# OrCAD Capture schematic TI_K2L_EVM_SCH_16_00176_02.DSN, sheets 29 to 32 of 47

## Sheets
29 PAGE17 : K2L_SOC-FPGA-AMC-3: size C; title: FPGA, K2L SPI/TIM/UART, FPGA test conn
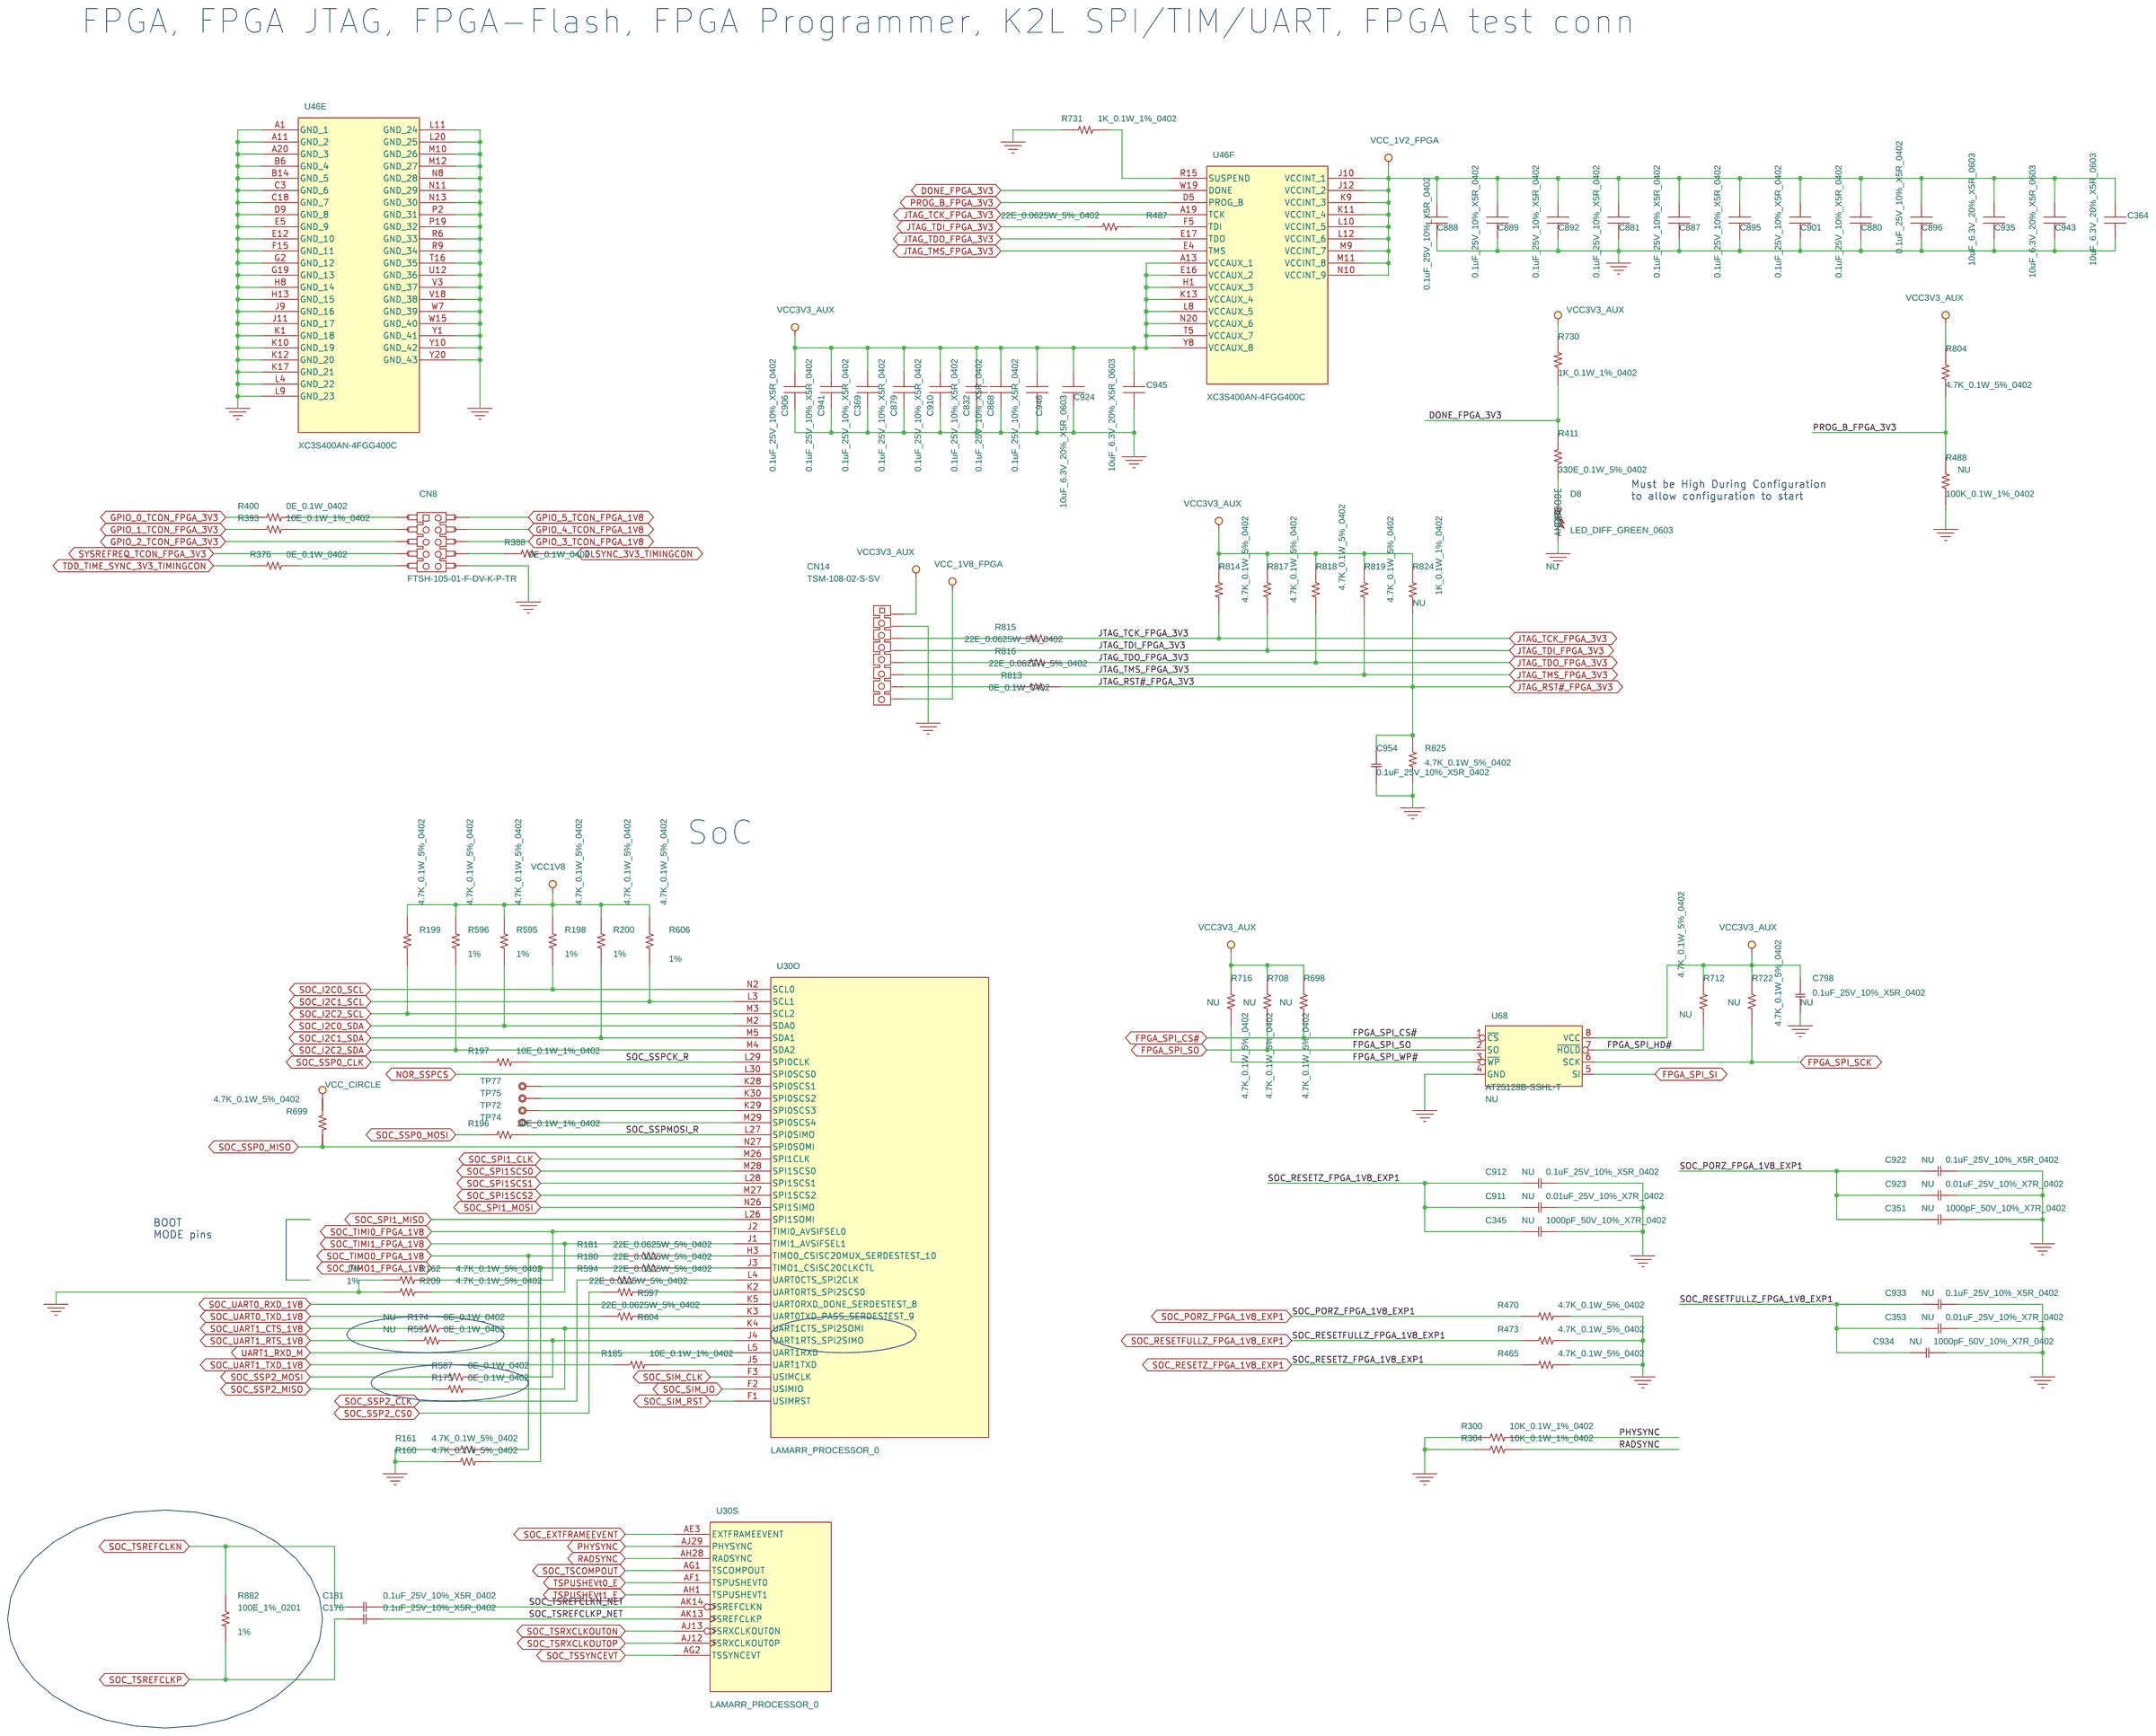
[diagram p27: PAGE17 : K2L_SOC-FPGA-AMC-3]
30 PAGE05 : POWER CONSUMPTION_C: title: POWER CONSUMPTION
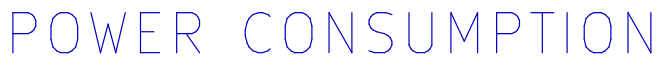
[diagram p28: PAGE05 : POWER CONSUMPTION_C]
31 PAGE02 : TABLE OF CONTENTS_C: title: TABLE OF CONTENTS
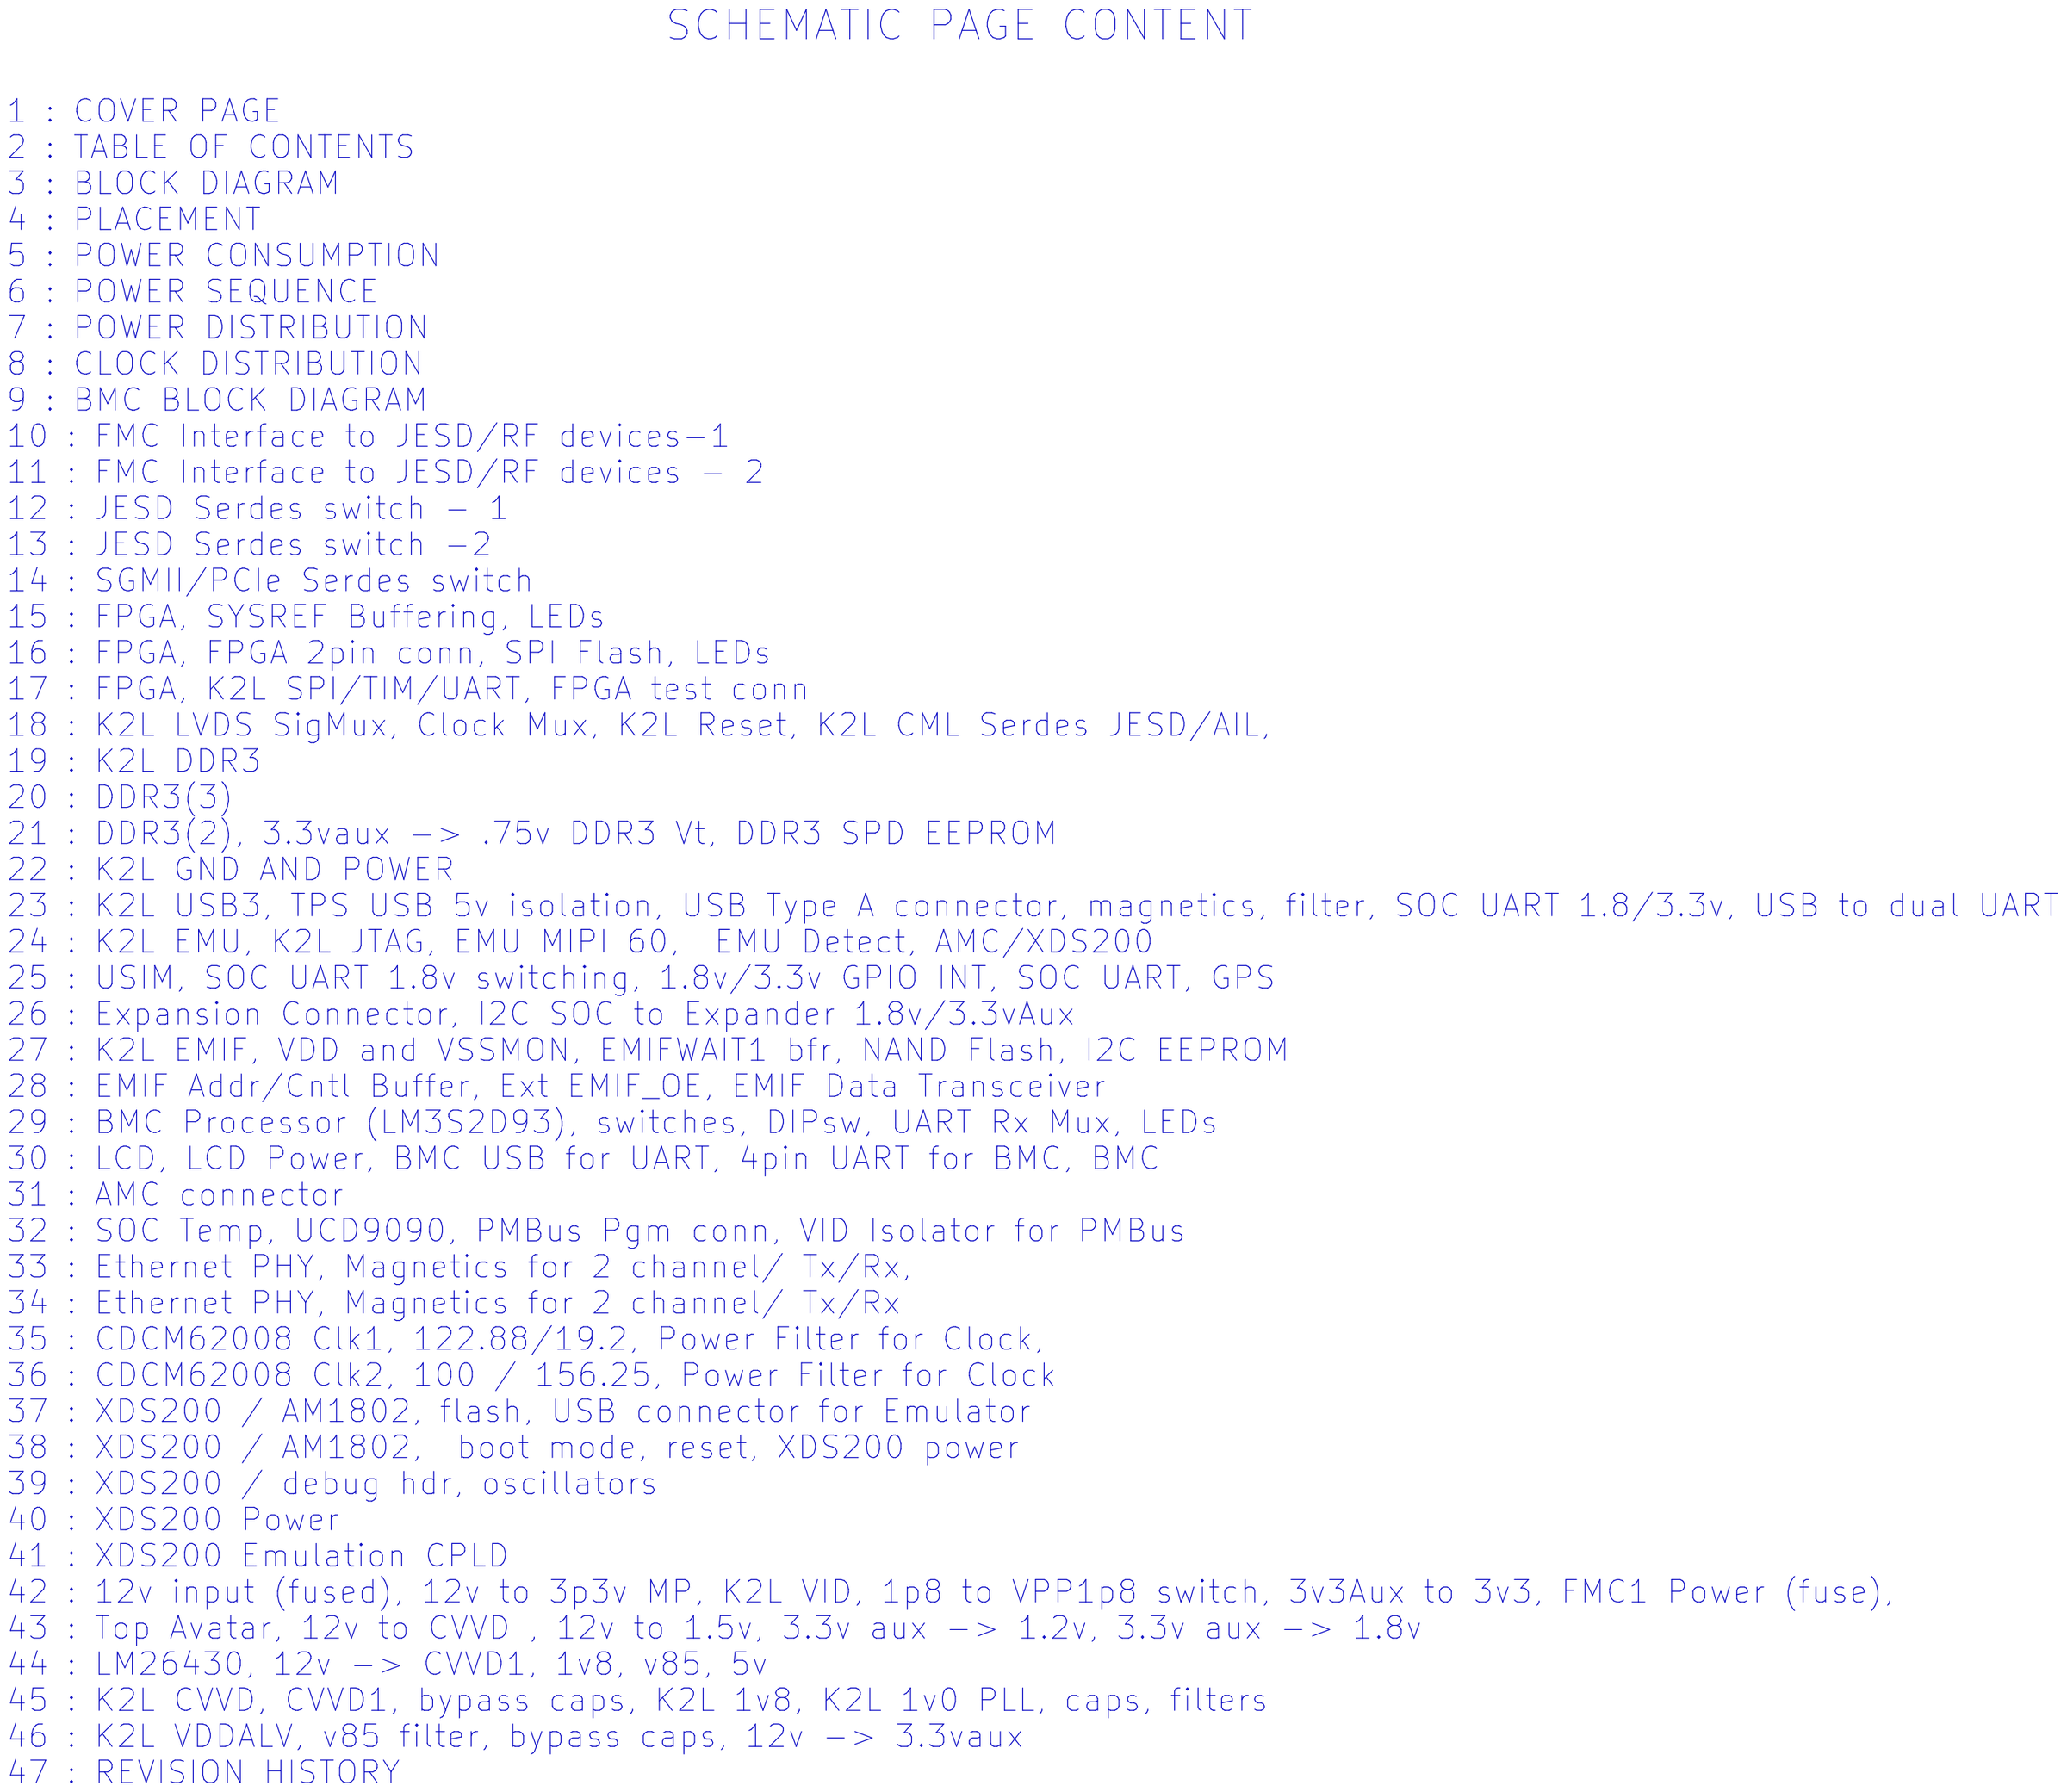
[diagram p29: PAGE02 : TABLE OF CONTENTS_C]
32 PAGE09 : BMC BLOCK DIAGRAM_C: title: BMC BLOCK DIAGRAM; note: K2E EVM
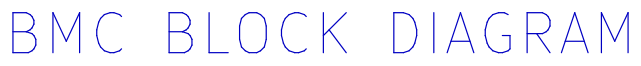
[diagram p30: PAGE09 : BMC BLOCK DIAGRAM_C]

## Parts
sheet PAGE17 : K2L_SOC-FPGA-AMC-3
C176  0.1uF_25V_10%_X5R_0402  [C0402]
C181  0.1uF_25V_10%_X5R_0402  [C0402]
C345  1000pF_50V_10%_X7R_0402  [C0402]
C351  1000pF_50V_10%_X7R_0402  [C0402]
C353  0.01uF_25V_10%_X7R_0402  [C0402]
C364  10uF_6.3V_20%_X5R_0603  [C0603]
C369  0.1uF_25V_10%_X5R_0402  [C0402]
C798  0.1uF_25V_10%_X5R_0402  [C0402]
C832  0.1uF_25V_10%_X5R_0402  [C0402]
C868  0.1uF_25V_10%_X5R_0402  [C0402]
C879  0.1uF_25V_10%_X5R_0402  [C0402]
C880  0.1uF_25V_10%_X5R_0402  [C0402]
C881  0.1uF_25V_10%_X5R_0402  [C0402]
C887  0.1uF_25V_10%_X5R_0402  [C0402]
C888  0.1uF_25V_10%_X5R_0402  [C0402]
C889  0.1uF_25V_10%_X5R_0402  [C0402]
C892  0.1uF_25V_10%_X5R_0402  [C0402]
C895  0.1uF_25V_10%_X5R_0402  [C0402]
C896  0.1uF_25V_10%_X5R_0402  [C0402]
C901  0.1uF_25V_10%_X5R_0402  [C0402]
C906  0.1uF_25V_10%_X5R_0402  [C0402]
C910  0.1uF_25V_10%_X5R_0402  [C0402]
C911  0.01uF_25V_10%_X7R_0402  [C0402]
C912  0.1uF_25V_10%_X5R_0402  [C0402]
C922  0.1uF_25V_10%_X5R_0402  [C0402]
C923  0.01uF_25V_10%_X7R_0402  [C0402]
C924  10uF_6.3V_20%_X5R_0603  [C0603]
C933  0.1uF_25V_10%_X5R_0402  [C0402]
C934  1000pF_50V_10%_X7R_0402  [C0402]
C935  10uF_6.3V_20%_X5R_0603  [C0603]
C941  0.1uF_25V_10%_X5R_0402  [C0402]
C943  10uF_6.3V_20%_X5R_0603  [C0603]
C945  10uF_6.3V_20%_X5R_0603  [C0603]
C946  0.1uF_25V_10%_X5R_0402  [C0402]
C954  0.1uF_25V_10%_X5R_0402  [C0402]
CN8  FTSH-105-01-F-DV-K-P-TR  [HD_5x2P_50_H235]
CN14  TSM-108-02-S-SV  [SAMTSM-108-01-S-SV]
D8  LED_DIFF_GREEN_0603  [LED_0603]
R160  4.7K_0.1W_5%_0402  [R0402]
R161  4.7K_0.1W_5%_0402  [R0402]
R162  4.7K_0.1W_5%_0402  [R0402]
R174  0E_0.1W_0402  [R0402]
R175  0E_0.1W_0402  [R0402]
R180  22E_0.0625W_5%_0402  [R0402]
R181  22E_0.0625W_5%_0402  [R0402]
R185  10E_0.1W_1%_0402  [R0402]
R196  10E_0.1W_1%_0402  [R0402]
R197  10E_0.1W_1%_0402  [R0402]
R198  4.7K_0.1W_5%_0402  [R0402]
R199  4.7K_0.1W_5%_0402  [R0402]
R200  4.7K_0.1W_5%_0402  [R0402]
R209  4.7K_0.1W_5%_0402  [R0402]
R300  10K_0.1W_1%_0402  [R0402]
R304  10K_0.1W_1%_0402  [R0402]
R376  0E_0.1W_0402  [R0402]
R388  0E_0.1W_0402  [R0402]
R393  10E_0.1W_1%_0402  [R0402]
R400  0E_0.1W_0402  [R0402]
R411  330E_0.1W_5%_0402  [R0402]
R465  4.7K_0.1W_5%_0402  [R0402]
R470  4.7K_0.1W_5%_0402  [R0402]
R473  4.7K_0.1W_5%_0402  [R0402]
R487  22E_0.0625W_5%_0402  [R0402]
R488  100K_0.1W_1%_0402  [R0402]
R587  0E_0.1W_0402  [R0402]
R591  0E_0.1W_0402  [R0402]
R594  22E_0.0625W_5%_0402  [R0402]
R595  4.7K_0.1W_5%_0402  [R0402]
R596  4.7K_0.1W_5%_0402  [R0402]
R597  22E_0.0625W_5%_0402  [R0402]
R604  22E_0.0625W_5%_0402  [R0402]
R606  4.7K_0.1W_5%_0402  [R0402]
R698  4.7K_0.1W_5%_0402  [R0402]
R699  4.7K_0.1W_5%_0402  [R0402]
R708  4.7K_0.1W_5%_0402  [R0402]
R712  4.7K_0.1W_5%_0402  [R0402]
R716  4.7K_0.1W_5%_0402  [R0402]
R722  4.7K_0.1W_5%_0402  [R0402]
R730  1K_0.1W_1%_0402  [R0402]
R731  1K_0.1W_1%_0402  [R0402]
R804  4.7K_0.1W_5%_0402  [R0402]
R813  0E_0.1W_0402  [R0402]
R814  4.7K_0.1W_5%_0402  [R0402]
R815  22E_0.0625W_5%_0402  [R0402]
R816  22E_0.0625W_5%_0402  [R0402]
R817  4.7K_0.1W_5%_0402  [R0402]
R818  4.7K_0.1W_5%_0402  [R0402]
R819  4.7K_0.1W_5%_0402  [R0402]
R824  1K_0.1W_1%_0402  [R0402]
R825  4.7K_0.1W_5%_0402  [R0402]
R882  100E_1%_0201  [RC0201_IPC7351_EINF]
TP72  TP  [TP-S40]
TP74  TP  [TP-S40]
TP75  TP  [TP-S40]
TP77  TP  [TP-S40]
U46  XC3S400AN-4FGG400C  [BGA400C100P20X20_2100X2100X243]  (sections A,B,C,D,E,F)
U68  AT25128B-SSHL-T  [SOIC_8P_50_193X236]
sheet PAGE24 : K2L_JTAG
U30  LAMARR_PROCESSOR_0  [SKTBGA_Z3566_SS900-RHFB-BGA080]  (sections A,B,C,D,E,F,G,H,I,J,K,L,M,N,O,P,Q,R,S,T,U)

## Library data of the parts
C176 C181 = 11_C_0: CAP CER 0.1UF 25V 10% X5R 0402; Avalue_Part_Number: E1123510400H; Distributor_name: DIGIKEY; Distributor_part_number: 445-4964-1-ND; EIC Part#: 03_00470_02; Manufacture: TDK Corporation; Manufacture Part Number: C1005X5R1E104K050BC; Manufacture(English): TDK Corporation; Manufacture_Part_Number: GRM155R71C104KA88D; Manufacturer: TDK Corporation; Manufacturer_Part_No: C1005X5R1E104K050BC; Mfg: Murata Electronics North America; Mfg Part#: 03_00470_02; Mfr_name: TDK Corporation; Mfr_part_number: C1005X5R1E104K050BC; Package: 0402; Price @ 1: 0.10000; Price @ 1K: 0.00420; ProcessType: SMT; Tolerance: 10%; Vendor: DIGIKEY; Vendor Part#: 445-4964-1-ND; Vendor_Part_No: 445-4964-1-ND; eI Part#: 03_00470_02
C345 C351 C934 = 11_C_0: CAP CER 1000PF 50V 10% X7R 0402; Advansus_Part_Number: 11G232110214030; Characteristic: 50V; Distributor_name: DIGIKEY; Distributor_part_number: 1276-1493-1-ND; EIC Part#: 03_00591_01; Manufacture: Samsung; Manufacture Part Number: CL05B102KB5NFNC; Manufacture(English): Samsung; Manufacture_Part_Number: CL05B102KB5NFNC; Manufacturer: Samsung; Manufacturer_Part_No: CL05B102KB5NFNC; Mfg: Samsung; Mfg Part#: CL05B102KB5NFNC; Mfr_name: Samsung; Mfr_part_number: CL05B102KB5NFNC; Mounting Status: NU; Mounting_Status: NU; Package: 0402; Part_Number: 1124510291; Price @ 1: 0.10000; Price @ 10K: 0.00216; Price @ 1K: 0.00309; ProcessType: SMT; Tolerance: 10%; Vendor: DIGIKEY; Vendor Part#: 1276-1493-1-ND; Vendor_Part_No: 1276-1493-1-ND; eI Part#: 03_00591_01
C353 C911 C923 = 11_C_0: CAP CER 10000PF 25V 10% X7R 0402; Advansus_Part_Number: 11G232110312030; Characteristic: 16V; Distributor_name: DIGIKEY; Distributor_part_number: 445-1260-1-ND; EIC Part#: 03_00029_04; GROUP: CPU1; Manufacture: TDK Corporation; Manufacture Part Number: C1005X7R1E103K; Manufacture(English): TDK Corporation; Manufacture_Part_Number: C1005X7R1E103K; Manufacturer: TDK Corporation; Manufacturer_Part_No: C1005X7R1E103K; Mfg: TDK Corporation; Mfg Part#: 03_00029_04; Mfr_name: TDK Corporation; Mfr_part_number: C1005X7R1E103K; Mounting Status: NU; Mounting_Status: NU; Package: 0402; Part_Number: 1121610790; Price @ 1: 0.10000; Price @ 10K: 0.00420; Price @ 1K: 0.00600; ProcessType: SMT; ROOM: CPU1; Tolerance: 10%; Vendor: DIGIKEY; Vendor_Part_No: 445-1260-1-ND; eI Part#: 03_00029_04
C364 C924 C935 C943 C945 = CAP: CAP CER 10UF 6.3V 20% X5R 0603; Distributor_name: DIGIKEY; Distributor_part_number: 587-3383-1-ND; EIC Part#: 03_00605_01; Manufacture: Taiyo Yuden; Manufacture Part Number: JMK107ABJ106MAHT; Manufacture(English): Taiyo Yuden; Manufacture_Part_Number: JMK107ABJ106MAHT; Manufacturer: Taiyo Yuden; Manufacturer_Part_No: JMK107ABJ106MAHT; Mfg: Taiyo Yuden; Mfg Part#: JMK107ABJ106MAHT; Mfr_name: Taiyo Yuden; Mfr_part_number: JMK107ABJ106MAHT; Price @ 1: 0.44000; Price @ 10K: 0.06105; Price @ 1K: 0.12650; RoHS Compliant?: RoHS Compliant; Vendor: DIGIKEY; Vendor_Part_No: 587-3383-1-ND; eI Part#: 03_00605_01
C369 C832 C868 C879-C881 C887-C889 C892 C895 C896 C901 C906 C910 C941 C946 = CAP: CAP CER 0.1UF 25V 10% X5R 0402; Distributor_name: DIGIKEY; Distributor_part_number: 445-4964-1-ND; EIC Part#: 03_00470_02; Manufacture: TDK Corporation; Manufacture Part Number: C1005X5R1E104K050BC; Manufacture(English): TDK Corporation; Manufacture_Part_Number: GRM155R61E104KA87D; Manufacturer: TDK Corporation; Manufacturer_Part_No: C1005X5R1E104K050BC; Mfg: Murata Electronics North America; Mfg Part#: 03_00470_02; Mfr_name: TDK Corporation; Mfr_part_number: C1005X5R1E104K050BC; Price @ 1: 0.10000; Price @ 1K: 0.00960; RoHS Compliant?: RoHS Compliant; Vendor: DIGIKEY; Vendor Part#: 445-4964-1-ND; Vendor_Part_No: 445-4964-1-ND; eI Part#: 03_00470_02
C798 = 11_C_0: CAP CER 0.1UF 25V 10% X5R 0402; Alt Mfg: Murata; Distributor_name: DIGIKEY; Distributor_part_number: 445-4964-1-ND; EIC Part#: 03_00470_02; Manufacture: TDK Corporation; Manufacture Part Number: C1005X5R1E104K050BC; Manufacture(English): TDK Corporation; Manufacture_Part_Number: GRM155R61E104KA87D; Manufacturer: TDK Corporation; Manufacturer_Part_No: C1005X5R1E104K050BC; Mfg: Murata Electronics North America; Mfg Part#: 03_00470_02; Mfr_name: TDK Corporation; Mfr_part_number: C1005X5R1E104K050BC; Mounting Status: NU; Mounting_Status: NU; Oper. Temp. Range: -55C to 85C; Package: 0402; Price @ 1: 0.10000; Price @ 1K: 0.00960; ProcessType: SMT; RoHS: Yes; Tolerance: 10%; Vendor: DIGIKEY; Vendor Part#: 445-4964-1-ND; Vendor_Part_No: 445-4964-1-ND; eI Part#: 03_00470_02
C912 C922 C933 = 11_C_0: CAP CER 0.1UF 25V 10% X5R 0402; Avalue_Part_Number: E1123510400H; Distributor_name: DIGIKEY; Distributor_part_number: 445-4964-1-ND; EIC Part#: 03_00470_02; Manufacture: TDK Corporation; Manufacture Part Number: C1005X5R1E104K050BC; Manufacture(English): TDK Corporation; Manufacture_Part_Number: GRM155R71C104KA88D; Manufacturer: TDK Corporation; Manufacturer_Part_No: C1005X5R1E104K050BC; Mfg: Murata Electronics North America; Mfg Part#: 03_00470_02; Mfr_name: TDK Corporation; Mfr_part_number: C1005X5R1E104K050BC; Mounting Status: NU; Mounting_Status: NU; Package: 0402; Price @ 1: 0.10000; Price @ 1K: 0.00420; ProcessType: SMT; Tolerance: 10%; Vendor: DIGIKEY; Vendor Part#: 445-4964-1-ND; Vendor_Part_No: 445-4964-1-ND; eI Part#: 03_00470_02
C954 = 11_C_0: CAP CER 0.1UF 25V 10% X5R 0402; Alt Mfg: Murata; Distributor_name: DIGIKEY; Distributor_part_number: 445-4964-1-ND; EIC Part#: 03_00470_02; Manufacture: TDK Corporation; Manufacture Part Number: C1005X5R1E104K050BC; Manufacture(English): TDK Corporation; Manufacture_Part_Number: GRM155R71C104KA88D; Manufacturer: TDK Corporation; Manufacturer_Part_No: C1005X5R1E104K050BC; Mfg: Murata Electronics North America; Mfg Part#: 03_00470_02; Mfr_name: TDK Corporation; Mfr_part_number: C1005X5R1E104K050BC; Oper. Temp. Range: -55C to 85C; Package: 0402; Price @ 1: 0.10000; Price @ 1K: 0.00420; ProcessType: SMT; RoHS: Yes; Tolerance: 10%; Vendor: DIGIKEY; Vendor Part#: 445-4964-1-ND; Vendor_Part_No: 445-4964-1-ND; eI Part#: 03_00470_02
CN8 = 1653_HD_5X2P_0: CONN HEADER 10POS DUAL .05 SMD; AVL_Part: AVL; Distributor_name: DIGIKEY; Distributor_part_number: FTSH-105-01-F-DV-K-P-TR-ND; EIC Part#: TBD; Manufacture: Samtec Inc; Manufacture(English): Samtec Inc; Manufacturer: Samtec Inc; Mfg: Samtec Inc; Mfg Part#: TBD; Mfr_name: Samtec Inc; Package: PH5x2P-S1.27; Part_Number: 1653004493; Price @ 1: 2.19000; Price @ 10K: 1.88000; Price @ 1K: 2.00000; ProcessType: SMT; Vendor: DIGIKEY; Vendor_Part_No: FTSH-105-01-F-DV-K-P-TR-ND; eI Part#: TBD
CN14 = 1653_JH8X1V_0: CONN HEADER 8POS .100 SGL GOLD; Distributor_name: DIGIKEY; Distributor_part_number: SAM1033-08-ND; EIC Part#: TBD; Manufacture: Samtec Inc; Manufacture(English): Samtec Inc; Manufacturer: Samtec Inc; Mfg Part#: 09_00660_01; Mfr_name: Samtec Inc; Package: PH8x1P-2.54; ProcessType: DIP; RoHS: Yes; Vendor: DIGIKEY; Vendor Part#: SAM1033-08-ND; Vendor_Part_No: SAM1033-08-ND; eI Part#: TBD
D8 = 130_LED_LED-0603_G_0: LED 565NM GRN DIFF 0603 SMD; Distributor_name: DIGIKEY; Distributor_part_number: 67-1549-1-ND; EIC Part#: 06_00007_01; Manufacture: Lumex Opto/Components Inc; Manufacture Part Number: SML-LX0603GW-TR; Manufacture(English): Lumex Opto/Components Inc; Manufacture_Part_Number: SML-LX0603GW-TR; Manufacturer: Lumex Opto/Components Inc; Manufacturer_Part_No: SML-LX0603GW-TR; Mfg Part#: 06_00007_01; Mfr_name: Lumex Opto/Components Inc; Mfr_part_number: SML-LX0603GW-TR; Mounting Status: NU; Mounting_Status: NU; Package: 0603; ProcessType: SMT; RoHS: Yes; Vendor: DIGIKEY; Vendor Part#: 67-1549-1-ND; Vendor_Part_No: 67-1549-1-ND; eI Part#: 06_00007_01
R160-R162 R198-R200 R209 R595 R596 R606 = 10_R_0: RES 4.7K OHM 1/10W 5% 0402 SMD; Alt Mfg: Yageo; Alt Mfg Part#: RC0402JR-074K7L; Distributor_name: DIGIKEY; Distributor_part_number: P4.7KJCT-ND; EIC Part#: 02_00023_01; Manufacture: Panasonic - ECG; Manufacture Part Number: ERJ-2GEJ472X; Manufacture(English): Panasonic - ECG; Manufacture_Part_Number: ERJ-2GEJ472X; Manufacturer: Panasonic - ECG; Manufacturer_Part_No: ERJ-2GEJ472X; Mfg Part#: 02_00023_01; Mfr_name: Panasonic - ECG; Mfr_part_number: ERJ-2GEJ472X; Oper. Temp. Range: -55C to 125C; Package: 0402; ProcessType: SMT; Remark: Alt part is 1/16W; RoHS: Yes; Tolerance: 1%; Vendor: DIGIKEY; Vendor Part#: P4.7KJCT-ND; Vendor_Part_No: P4.7KJCT-ND; eI Part#: 02_00023_01
R174 R591 = 10_R_0: RES 0.0 OHM 1/10W JUMP 0402 SMD; Distributor_name: DIGIKEY; Distributor_part_number: P0.0JCT-ND; EIC Part#: 02_00019_01; Manufacture: Panasonic - ECG; Manufacture Part Number: ERJ-2GE0R00X; Manufacture(English): Panasonic - ECG; Manufacture_Part_Number: ERJ-2GE0R00X; Manufacturer: Panasonic - ECG; Manufacturer_Part_No: ERJ-2GE0R00X; Mfg Part#: 02_00019_01; Mfr_name: Panasonic - ECG; Mfr_part_number: ERJ-2GE0R00X; Mounting Status: NU; Mounting_Status: NU; Oper. Temp. Range: -55C to 125C; Package: 0402; ProcessType: SMT; Remark: Alt part is 1/16W; RoHS: Yes; Tolerance: 5%; Vendor: DIGIKEY; Vendor Part#: P0.0JCT-ND; Vendor_Part_No: P0.0JCT-ND; eI Part#: 02_00019_01
R175 R587 = 10_R_0: RES 0.0 OHM 1/10W JUMP 0402 SMD; Distributor_name: DIGIKEY; Distributor_part_number: P0.0JCT-ND; EIC Part#: 02_00019_01; Manufacture: Panasonic - ECG; Manufacture Part Number: ERJ-2GE0R00X; Manufacture(English): Panasonic - ECG; Manufacture_Part_Number: ERJ-2GE0R00X; Manufacturer: Panasonic - ECG; Manufacturer_Part_No: ERJ-2GE0R00X; Mfg Part#: 02_00019_01; Mfr_name: Panasonic - ECG; Mfr_part_number: ERJ-2GE0R00X; Oper. Temp. Range: -55C to 125C; Package: 0402; ProcessType: SMT; Remark: Alt part is 1/16W; RoHS: Yes; Tolerance: 5%; Vendor: DIGIKEY; Vendor Part#: P0.0JCT-ND; Vendor_Part_No: P0.0JCT-ND; eI Part#: 02_00019_01
R180 R181 R604 = 10_R_0: RES 22 OHM 1/16W 1% 0402 SMD; Characteristic: 5%; Distributor_name: DIGIKEY; Distributor_part_number: P22JCT-ND; EIC Part#: 02_00233_01; Manufacture: Panasonic - ECG; Manufacture Part Number: ERJ-2GEJ220X; Manufacture(English): Panasonic - ECG; Manufacture_Part_Number: ERJ-2GEJ220X; Manufacturer: Panasonic - ECG; Manufacturer_Part_No: ERJ-2GEJ220X; Mfg: Panasonic - ECG; Mfg Part#: ERJ-2GEJ220X; Mfr_name: Panasonic - ECG; Mfr_part_number: ERJ-2GEJ220X; Oper. Temp. Range: -55C to 125C; Package: 0402; ProcessType: SMT; RoHS: Yes; Tolerance: 5%; Vendor: DIGIKEY; Vendor Part#: P22JCT-ND; Vendor_Part_No: P22JCT-ND; eI Part#: 02_00233_01
R185 R196 R197 = 10_R_0: RES 10.0 OHM 1/10W 1% 0402 SMD; Characteristic: 5%; Distributor_name: DIGIKEY; Distributor_part_number: P10.0LCT-ND; EIC Part#: 02_00348_01; Manufacture: Panasonic - ECG; Manufacture Part Number: ERJ-2RKF10R0X; Manufacture(English): Panasonic - ECG; Manufacture_Part_Number: ERJ-2RKF10R0X; Manufacturer: Panasonic - ECG; Manufacturer_Part_No: ERJ-2RKF10R0X; Mfg: Panasonic Electronic Components; Mfg Part#: ERJ-2RKF10R0X; Mfr_name: Panasonic - ECG; Mfr_part_number: ERJ-2RKF10R0X; Package: 0402; Part_Number: 105A701004; Price @ 1: 0.10000; Price @ 10K: 0.00248; Price @ 1K: 0.00480; ProcessType: SMT; Tolerance: 5%; Vendor: DIGIKEY; Vendor_Part_No: P10.0LCT-ND; eI Part#: 02_00348_01
R300 R304 = 10_R_0: RES 10K OHM 1/10W 1% 0402 SMD; Characteristic: 1%; Distributor_name: DIGIKEY; Distributor_part_number: P10.0KLCT-ND; EIC Part#: 02_00027_01; MOUNTED: <MOUNTED>; Manufacture: Panasonic - ECG; Manufacture Part Number: ERJ-2RKF1002X; Manufacture(English): Panasonic - ECG; Manufacture_Part_Number: ERJ-2RKF1002X; Manufacturer: Panasonic - ECG; Manufacturer_Part_No: ERJ-2RKF1002X; Mfg: PANASONIC ELECTRONIC COMPONENTS (VA); Mfg Part#: 02_00027_01; Mfr_name: Panasonic - ECG; Mfr_part_number: ERJ-2RKF1002X; Package: 0402; Part_Number: 105A50103A; Price @ 1: 0.10000; Price @ 10K: 0.00347; Price @ 1K: 0.00672; ProcessType: SMT; Tolerance: 1%; Vendor: DIGIKEY; Vendor_Part_No: P10.0KLCT-ND; eI Part#: 02_00027_01
R376 R388 R400 R813 = 10_R_0: RES 0.0 OHM 1/10W JUMP 0402 SMD; Alt Mfg: Yageo; Distributor_name: DIGIKEY; Distributor_part_number: P0.0JCT-ND; EIC Part#: 02_00019_01; Manufacture: Panasonic - ECG; Manufacture Part Number: ERJ-2GE0R00X; Manufacture(English): Panasonic - ECG; Manufacture_Part_Number: ERJ-2GE0R00X; Manufacturer: Panasonic - ECG; Manufacturer_Part_No: ERJ-2GE0R00X; Mfg Part#: 02_00019_01; Mfr_name: Panasonic - ECG; Mfr_part_number: ERJ-2GE0R00X; Oper. Temp. Range: -55C to 125C; Package: 0402; ProcessType: SMT; Remark: Alt part is 1/16W; RoHS: Yes; Tolerance: 5%; Vendor: DIGIKEY; Vendor Part#: P0.0JCT-ND; Vendor_Part_No: P0.0JCT-ND; eI Part#: 02_00019_01
R393 = 10_R_0: RES 10.0 OHM 1/10W 1% 0402 SMD; Distributor_name: DIGIKEY; Distributor_part_number: P10.0LCT-ND; EIC Part#: 02_00348_01; Manufacture: Panasonic - ECG; Manufacture Part Number: ERJ-2RKF10R0X; Manufacture(English): Panasonic - ECG; Manufacture_Part_Number: ERJ-2RKF10R0X; Manufacturer: Panasonic - ECG; Manufacturer_Part_No: ERJ-2RKF10R0X; Mfg: Panasonic Electronic Components; Mfg Part#: 02_00348_01; Mfr_name: Panasonic - ECG; Mfr_part_number: ERJ-2RKF10R0X; Price @ 1: 0.10000; Price @ 10K: 0.00347; Price @ 1K: 0.00672; Vendor: DIGIKEY; Vendor_Part_No: P10.0LCT-ND; eI Part#: 02_00027_01
R411 = 10_R_0: RES 330 OHM 1/10W 5% 0402 SMD; Alt Mfg: Yageo; Alt Mfg Part#: RC0402JR-07330RL; Distributor_name: DIGIKEY; Distributor_part_number: P330JCT-ND; EIC Part#: 02_00032_01; Manufacture: Panasonic - ECG; Manufacture Part Number: ERJ-2GEJ331X; Manufacture(English): Panasonic - ECG; Manufacture_Part_Number: ERJ-2GEJ331X; Manufacturer: Panasonic - ECG; Manufacturer_Part_No: ERJ-2GEJ331X; Mfg Part#: 02_00032_01; Mfr_name: Panasonic - ECG; Mfr_part_number: ERJ-2GEJ331X; Mounting Status: NU; Mounting_Status: NU; Package: 0402; ProcessType: SMT; Remark: Alt part is 1/16W; RoHS: Yes; Tolerance: 5%; Vendor: DIGIKEY; Vendor Part#: P330JCT-ND; Vendor_Part_No: P330JCT-ND; eI Part#: 02_00734_01
R465 R470 R473 R699 = 10_R_0: RES 4.7K OHM 1/10W 5% 0402 SMD; Advansus_Part_Number: 10G212472004030; Avalue_Part_Number: E1050704720H; Characteristic: 5%; Distributor_name: DIGIKEY; Distributor_part_number: P4.7KJCT-ND; EIC Part#: 02_00023_01; MOUNTED: <MOUNTED>; Manufacture: Panasonic - ECG; Manufacture Part Number: ERJ-2GEJ472X; Manufacture(English): Panasonic - ECG; Manufacture_Part_Number: ERJ-2GEJ472X; Manufacturer: Panasonic - ECG; Manufacturer_Part_No: ERJ-2GEJ472X; Mfg: Panasonic Electronic Components; Mfg Part#: 02_00266_01; Mfr_name: Panasonic - ECG; Mfr_part_number: ERJ-2GEJ472X; Package: 0402; Part_Number: 105A747014; Price @ 1: 0.10000; Price @ 10K: 0.00347; Price @ 1K: 0.00672; ProcessType: SMT; Tolerance: 5%; Vendor: DIGIKEY; Vendor_Part_No: P4.7KJCT-ND; eI Part#: 02_00023_01
R487 R815 R816 = 10_R_0: RES 22 OHM 1/16W 1% 0402 SMD; Distributor_name: DIGIKEY; Distributor_part_number: P22JCT-ND; EIC Part#: 02_00233_01; Manufacture: Panasonic - ECG; Manufacture Part Number: ERJ-2GEJ220X; Manufacture(English): Panasonic - ECG; Manufacture_Part_Number: ERJ-2GEJ220X; Manufacturer: Panasonic - ECG; Manufacturer_Part_No: ERJ-2GEJ220X; Mfg: Panasonic - ECG; Mfg Part#: ERJ-2GEJ220X; Mfr_name: Panasonic - ECG; Mfr_part_number: ERJ-2GEJ220X; Oper. Temp. Range: -55C to 125C; Package: 0402; ProcessType: SMT; Remark: Alt part is 1/16W; RoHS: Yes; Tolerance: 5%; Vendor: DIGIKEY; Vendor Part#: P22JCT-ND; Vendor_Part_No: P22JCT-ND; eI Part#: 02_00233_01
R488 = 10_R_0: RES 100K OHM 1/10W 1% 0402 SMD; Alt Mfg: Yageo; Alt Mfg Part#: RC0402FR-07100KL; Distributor_name: DIGIKEY; Distributor_part_number: P100KLCT-ND; EIC Part#: 02_00262_01; Manufacture: Panasonic - ECG; Manufacture Part Number: ERJ-2RKF1003X; Manufacture(English): Panasonic - ECG; Manufacture_Part_Number: ERJ-2RKF1003X; Manufacturer: Panasonic - ECG; Manufacturer_Part_No: ERJ-2RKF1003X; Mfg Part#: 02_00262_01; Mfr_name: Panasonic - ECG; Mfr_part_number: ERJ-2RKF1003X; Mounting Status: NU; Mounting_Status: NU; Oper. Temp. Range: ±100ppm/°C; Package: 0402; ProcessType: SMT; RoHS: Yes; Tolerance: 1%; Vendor: DIGIKEY; Vendor Part#: P100KLCT-ND; Vendor_Part_No: P100KLCT-ND; eI Part#: 02_00266_01
R594 R597 = 10_R_0: RES 22 OHM 1/16W 1% 0402 SMD; Characteristic: 5%; Distributor_name: DIGIKEY; Distributor_part_number: P22JCT-ND; EIC Part#: 02_00233_01; MOUNTED: <MOUNTED>; Manufacture: Panasonic - ECG; Manufacture Part Number: ERJ-2GEJ220X; Manufacture(English): Panasonic - ECG; Manufacture_Part_Number: ERJ-2GEJ220X; Manufacturer: Panasonic - ECG; Manufacturer_Part_No: ERJ-2GEJ220X; Mfg: Panasonic - ECG; Mfg Part#: ERJ-2GEJ220X; Mfr_name: Panasonic - ECG; Mfr_part_number: ERJ-2GEJ220X; Package: 0402; Part_Number: 105A722064; Price @ 1: 0.10000; Price @ 10K: 0.00132; Price @ 1K: 0.00233; ProcessType: SMT; Tolerance: 5%; Vendor: DIGIKEY; Vendor Part#: P22JCT-ND; Vendor_Part_No: P22JCT-ND; eI Part#: 02_00233_01
R698 R708 R712 R716 R722 = 10_R_0: RES 4.7K OHM 1/10W 5% 0402 SMD; Alt Mfg: Yageo; Alt Mfg Part#: RC0402JR-074K7L; Distributor_name: DIGIKEY; Distributor_part_number: P4.7KJCT-ND; EIC Part#: 02_00023_01; Manufacture: Panasonic - ECG; Manufacture Part Number: ERJ-2GEJ472X; Manufacture(English): Panasonic - ECG; Manufacture_Part_Number: ERJ-2GEJ472X; Manufacturer: Panasonic - ECG; Manufacturer_Part_No: ERJ-2GEJ472X; Mfg Part#: 02_00023_01; Mfr_name: Panasonic - ECG; Mfr_part_number: ERJ-2GEJ472X; Mounting Status: NU; Mounting_Status: NU; Oper. Temp. Range: -55C to 125C; Package: 0402; ProcessType: SMT; Remark: Alt part is 1/16W; RoHS: Yes; Tolerance: 5%; Vendor: DIGIKEY; Vendor Part#: P4.7KJCT-ND; Vendor_Part_No: P4.7KJCT-ND; eI Part#: 02_00023_01
R730 R731 = 10_R_0: RES 1.00K OHM 1/10W 1% 0402 SMD; Alt Mfg: Yageo; Distributor_name: DIGIKEY; Distributor_part_number: P1.00KLCT-ND; EIC Part#: 02_00045_01; MOUNTED: <MOUNTED>; Manufacture: Panasonic - ECG; Manufacture Part Number: ERJ-2RKF1001X; Manufacture(English): Panasonic - ECG; Manufacture_Part_Number: ERJ-2RKF1001X; Manufacturer: Panasonic - ECG; Manufacturer_Part_No: ERJ-2RKF1001X; Mfg Part#: 02_00045_01; Mfr_name: Panasonic - ECG; Mfr_part_number: ERJ-2RKF1001X; Oper. Temp. Range: -55C to 125C; Package: 0402; ProcessType: SMT; RoHS: Yes; Tolerance: 1%; Vendor: DIGIKEY; Vendor Part#: P1.00KLCT-ND; Vendor_Part_No: P1.00KLCT-ND; eI Part#: 02_00045_01
R804 = 10_R_0: RES 4.7K OHM 1/10W 5% 0402 SMD; Alt Mfg: Yageo; Alt Mfg Part#: RC0402JR-074K7L; Distributor_name: DIGIKEY; Distributor_part_number: P4.7KJCT-ND; EIC Part#: 02_00023_01; Manufacture: Panasonic - ECG; Manufacture Part Number: ERJ-2GEJ472X; Manufacture(English): Panasonic - ECG; Manufacture_Part_Number: ERJ-2GEJ472X; Manufacturer: Panasonic - ECG; Manufacturer_Part_No: ERJ-2GEJ472X; Mfg Part#: 02_00023_01; Mfr_name: Panasonic - ECG; Mfr_part_number: ERJ-2GEJ472X; Oper. Temp. Range: -55C to 125C; Package: 0402; ProcessType: SMT; Remark: Alt part is 1/16W; RoHS: Yes; Tolerance: 5%; Vendor: DIGIKEY; Vendor Part#: P4.7KJCT-ND; Vendor_Part_No: P4.7KJCT-ND; eI Part#: 02_00023_01
R814 R817-R819 R825 = 10_R_0: RES 4.7K OHM 1/10W 5% 0402 SMD; Alt Mfg: Yageo; Alt Mfg Part#: RC0402JR-074K7L; Distributor_name: DIGIKEY; Distributor_part_number: P4.7KJCT-ND; EIC Part#: 02_00023_01; MOUNTED: <MOUNTED>; Manufacture: Panasonic - ECG; Manufacture Part Number: ERJ-2GEJ472X; Manufacture(English): Panasonic - ECG; Manufacture_Part_Number: ERJ-2GEJ472X; Manufacturer: Panasonic - ECG; Manufacturer_Part_No: ERJ-2GEJ472X; Mfg Part#: 02_00023_01; Mfr_name: Panasonic - ECG; Mfr_part_number: ERJ-2GEJ472X; Oper. Temp. Range: -55C to 125C; Package: 0402; ProcessType: SMT; Remark: Alt part is 1/16W; RoHS: Yes; Tolerance: 5%; Vendor: DIGIKEY; Vendor Part#: P4.7KJCT-ND; Vendor_Part_No: P4.7KJCT-ND; eI Part#: 02_00023_01
R824 = 10_R_0: RES 1.00K OHM 1/10W 1% 0402 SMD; Alt Mfg: Yageo; Distributor_name: DIGIKEY; Distributor_part_number: P1.00KLCT-ND; EIC Part#: 02_00045_01; Manufacture: Panasonic - ECG; Manufacture Part Number: ERJ-2RKF1001X; Manufacture(English): Panasonic - ECG; Manufacture_Part_Number: ERJ-2RKF1001X; Manufacturer: Panasonic - ECG; Manufacturer_Part_No: ERJ-2RKF1001X; Mfg Part#: 02_00045_01; Mfr_name: Panasonic - ECG; Mfr_part_number: ERJ-2RKF1001X; Mounting Status: NU; Mounting_Status: NU; Oper. Temp. Range: -55C to 125C; Package: 0402; ProcessType: SMT; RoHS: Yes; Tolerance: 1%; Vendor: DIGIKEY; Vendor Part#: P1.00KLCT-ND; Vendor_Part_No: P1.00KLCT-ND; eI Part#: 02_00045_01
R882 = 10_R_0: RES 100 OHM 1/20W 1% 0201 SMD; Characteristic: 1%; Distributor_name: DIGIKEY; EIC Part#: 02_00043_02; Manufacture: Panasonic - ECG; Manufacture Part Number: ERJ-1GEF1000C; Manufacture(English): Panasonic - ECG; Manufacture_Part_Number: ERJ-1GEF1000C; Manufacturer: Panasonic - ECG; Manufacturer_Part_No: ERJ-1GEF1000C; Mfg: Panasonic - ECG; Mfg Part#: ERJ-1GEF1000C; Mfr_name: Panasonic - ECG; Mfr_part_number: ERJ-1GEF1000C; Package: 0201; ProcessType: SMT; RoHS: Yes; Tolerance: 1%; Vendor: Digikey; Vendor Part#: P100ABCT-ND; Vendor_Part_No: P100ABCT-ND; eI Part#: 02_00043_02
TP72 TP74 TP75 TP77 = 00_TP28_0: TEST PAD TP; Advansus_Part_Number: 0030000003; Avalue_Part_Number: 0030000003; Distributor_name: NA; Distributor_part_number: NA; EIC Part#: NA; Manufacture: NA; Manufacture Part Number: NA; Manufacture(English): NA; Manufacture_Part_Number: NA; Manufacturer: NA; Manufacturer_Part_No: NA; Mfg: NA; Mfg Part#: NA; Mfr_name: NA; Mfr_part_number: NA; Part_Number: 0030000003; Price @ 1: NA; Price @ 10K: NA; Price @ 1K: NA; ProcessType: SMT; Vendor: NA; Vendor_Part_No: NA; eI Part#: NA
U46 = XC3S400AN-4FGG400C: IC SPARTAN-3AN FPGA 400K 400FBGA; Color: Default; Distributor_name: DIGIKEY; Distributor_part_number: 122-1554-ND; EIC Part#: 01_01149_01; Location X-Coordinate: 0; Location Y-Coordinate: 0; Manufacture: Xilinx Inc; Manufacture(English): Xilinx Inc; Manufacturer: Xilinx Inc; Mfg: Xilinx Inc; Mfg Part#: 01_01149_01; Mfr_name: Xilinx Inc; Price @ 1: 27.86000; Primitive: DEFAULT; SPLIT_INST: TRUE; SWAP_INFO: (S1+S2+S3+S4+S5+S6); Vendor: DIGIKEY; Vendor_Part_No: 122-1554-ND; eI Part#: 01_01138_01
U68 = 141_ATMEL_AT25128B-SSHL-B: IC EEPROM 128KBIT 20MHZ 8SOIC; Distributor_name: DIGIKEY; Distributor_part_number: AT25128B-SSHL-TCT-ND; EIC Part#: TBD; Manufacture: Atmel; Manufacture(English): Atmel; Manufacturer: Atmel; Mfg: Atmel; Mfg Part#: TBD; Mfr_name: Atmel; Mounting Status: NU; Mounting_Status: NU; Oper. Temp. Range: -40°C ~ 85°C; Package: SOIC8; Price @ 1: 1.18000; Price @ 10K: 0.66000; Price @ 1K: 0.73150; ProcessType: SMT; RoHS: Yes; Vendor: DIGIKEY; Vendor Part#: AT25128B-SSHL-B-ND; Vendor_Part_No: AT25128B-SSHL-TCT-ND; eI Part#: TBD
U30 = LAMARR_PROCESSOR_7: LAMARR-SoC 900BGA 4DSP + 2ARM; Color: Default; Distributor_name: TBD; Distributor_part_number: TBD; EIC Part#: TBD; Location X-Coordinate: 0; Location Y-Coordinate: 0; Manufacture: TI; Manufacture Part Number: TCI6630K2L; Manufacture(English): TI; Manufacture_Part_Number: TCI6630K2L; Manufacturer: TI; Manufacturer_Part_No: TCI6630K2L; Mfg: TI; Mfg Part#: TBD; Mfr_name: TI; Mfr_part_number: LAMARR-SoC; Price @ 1: TBD; Price @ 10K: TBD; Price @ 1K: TBD; Primitive: DEFAULT; SPLIT_INST: TRUE; SWAP_INFO: (S1+S2+S3+S4+S5+S6+S7+S8+S9+S10+S11+S12+S13+S14+S15+S16+S17+S18+S19+S20+S21); Vendor: TBD; Vendor_Part_No: TBD; eI Part#: TBD

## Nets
GND: C345.1 C351.1 C353.2 C364.2 C369.2 C798.1 C832.2 C868.2 C879.2 C880.2 C881.2 C887.2 C888.2 C889.2 C892.2 C895.2 C896.2 C901.2 C906.2 C910.2 C911.2 C912.2 C922.2 C923.2 C924.2 C933.2 C934.1 C935.2 C941.2 C943.2 C945.2 C946.2 C954.2 CN8.10 CN14.2 D8.2(CATHODE) R160.2 R161.2 R162.2 R209.2 R300.2 R304.2 R465.1 R470.1 R473.1 R488.1 R731.2 R825.2 U46.A1(GND_1) U46.A11(GND_2) U46.A20(GND_3) U46.B6(GND_4) U46.B14(GND_5) U46.C3(GND_6) U46.C18(GND_7) U46.D9(GND_8) U46.E5(GND_9) U46.E12(GND_10) U46.F15(GND_11) U46.G2(GND_12) U46.G19(GND_13) U46.H8(GND_14) U46.H13(GND_15) U46.J9(GND_16) U46.J11(GND_17) U46.K1(GND_18) U46.K10(GND_19) U46.K12(GND_20) U46.K17(GND_21) U46.L4(GND_22) U46.L9(GND_23) U46.L11(GND_24) U46.L20(GND_25) U46.M10(GND_26) U46.M12(GND_27) U46.N8(GND_28) U46.N11(GND_29) U46.N13(GND_30) U46.P2(GND_31) U46.P19(GND_32) U46.R6(GND_33) U46.R9(GND_34) U46.T16(GND_35) U46.U12(GND_36) U46.V3(GND_37) U46.V18(GND_38) U46.W7(GND_39) U46.W15(GND_40) U46.Y1(GND_41) U46.Y10(GND_42) U46.Y20(GND_43) U68.4(GND) ; also on sheet 1 2 3 4 5 6 8 10 11 12 13 14 15 16 17 18 19 20 21 22 24 25 26 27 28 33 34 35 36 37 40 41 42 43 45 46 47
VCC1V8: R198.2 R199.2 R200.2 R595.2 R596.2 R606.2 R699.1 ; also on sheet 2 6 8 11 19 21 22 25 26 27 33 34 36 37 41
VCC3V3_AUX: C369.1 C798.2 C832.1 C868.1 C879.1 C906.1 C910.1 C924.1 C941.1 C945.1 C946.1 CN14.1 R698.1 R708.1 R712.1 R716.1 R722.1 R730.2 R804.2 R814.2 R817.2 R818.2 R819.2 R824.2 U46.A13(VCCAUX_1) U46.E16(VCCAUX_2) U46.H1(VCCAUX_3) U46.K13(VCCAUX_4) U46.L8(VCCAUX_5) U46.N20(VCCAUX_6) U46.T5(VCCAUX_7) U46.Y8(VCCAUX_8) U68.8(VCC) ; also on sheet 2 4 6 8 11 12 13 16 18 19 22 25 26 27 28 33 35 37 40 45 47
VCC_1V2_FPGA: C364.1 C880.1 C881.1 C887.1 C888.1 C889.1 C892.1 C895.1 C896.1 C901.1 C935.1 C943.1 U46.J10(VCCINT_1) U46.J12(VCCINT_2) U46.K9(VCCINT_3) U46.K11(VCCINT_4) U46.L10(VCCINT_5) U46.L12(VCCINT_6) U46.M9(VCCINT_7) U46.M11(VCCINT_8) U46.N10(VCCINT_9) ; also on sheet 35
VCC_1V8_FPGA: CN14.8 ; also on sheet 27 28 35
DLSYNC_3V3_TIMINGCON: R388.2 ; also on sheet 27
DONE_FPGA_3V3: R411.2 R730.1 U46.W19(DONE) ; also on sheet 27
FPGA_SPI_CS#: R698.2 U68.1(~{CS}) ; also on sheet 27
FPGA_SPI_HD#: R712.2 U68.7(~{HOLD})
FPGA_SPI_SCK: R722.2 U68.6(SCK) ; also on sheet 27
FPGA_SPI_SI: U68.5(SI) ; also on sheet 27
FPGA_SPI_SO: R708.2 U68.2(SO) ; also on sheet 27
FPGA_SPI_WP#: R716.2 U68.3(~{WP})
GPIO_0_TCON_FPGA_3V3: R400.1 ; also on sheet 27
GPIO_1_TCON_FPGA_3V3: R393.1 ; also on sheet 27
GPIO_2_TCON_FPGA_3V3: CN8.5 ; also on sheet 27
GPIO_3_TCON_FPGA_1V8: CN8.6 ; also on sheet 28
GPIO_4_TCON_FPGA_1V8: CN8.4 ; also on sheet 28
GPIO_5_TCON_FPGA_1V8: CN8.2 ; also on sheet 28
JTAG_RST#_FPGA_3V3: C954.1 R813.2 R824.1 R825.1 ; also on sheet 27
JTAG_TCK_FPGA_3V3: R814.1 R815.1 U46.A19(TCK)
JTAG_TDI_FPGA_3V3: CN14.4 R487.2 R817.1
JTAG_TDO_FPGA_3V3: R816.1 R818.1 U46.E17(TDO)
JTAG_TMS_FPGA_3V3: CN14.6 R819.1 U46.E4(TMS)
NOR_SSPCS: U30.L30(SPI0SCS0) ; also on sheet 27
PHYSYNC: R300.1 U30.AJ29(PHYSYNC) ; also on sheet 18 26
PROG_B_FPGA_3V3: R488.2 R804.1 U46.D5(PROG_B)
RADSYNC: R304.1 U30.AH28(RADSYNC) ; also on sheet 18 26
SOC_EXTFRAMEEVENT: U30.AE3(EXTFRAMEEVENT) ; also on sheet 28
SOC_I2C0_SCL: R198.1 U30.N2(SCL0) ; also on sheet 41
SOC_I2C0_SDA: R595.1 U30.M2(SDA0) ; also on sheet 41
SOC_I2C1_SCL: R606.1 U30.L3(SCL1) ; also on sheet 19 28
SOC_I2C1_SDA: R200.1 U30.M5(SDA1) ; also on sheet 19 28
SOC_I2C2_SCL: R199.1 U30.M3(SCL2) ; also on sheet 26
SOC_I2C2_SDA: R596.1 U30.M4(SDA2) ; also on sheet 26
SOC_PORZ_FPGA_1V8_EXP1: C351.2 C922.1 C923.1 R470.2 ; also on sheet 16 28
SOC_RESETFULLZ_FPGA_1V8_EXP1: C353.1 C933.1 C934.2 R473.2 ; also on sheet 16 28
SOC_RESETZ_FPGA_1V8_EXP1: C345.2 C911.1 C912.1 R465.2 ; also on sheet 16 28
SOC_SIM_CLK: U30.F3(USIMCLK) ; also on sheet 22
SOC_SIM_IO: U30.F2(USIMIO) ; also on sheet 22
SOC_SIM_RST: U30.F1(USIMRST) ; also on sheet 22
SOC_SPI1_CLK: U30.M26(SPI1CLK) ; also on sheet 11 28
SOC_SPI1_MISO: U30.L26(SPI1SOMI) ; also on sheet 28
SOC_SPI1_MOSI: U30.N26(SPI1SIMO) ; also on sheet 11 28
SOC_SPI1SCS0: U30.M28(SPI1SCS0) ; also on sheet 11
SOC_SPI1SCS1: U30.L28(SPI1SCS1) ; also on sheet 28
SOC_SPI1SCS2: U30.M27(SPI1SCS2) ; also on sheet 28
SOC_SSP0_CLK: R197.1 ; also on sheet 27
SOC_SSP0_MISO: R699.2 U30.N27(SPI0SOMI) ; also on sheet 27
SOC_SSP0_MOSI: R196.1 ; also on sheet 27
SOC_SSP2_CLK: R594.2 ; also on sheet 26
SOC_SSP2_CS0: R597.2 ; also on sheet 26
SOC_SSP2_MISO: R175.1 ; also on sheet 26
SOC_SSP2_MOSI: R587.1 ; also on sheet 26
SOC_SSPCK_R: R197.2 U30.L29(SPI0CLK)
SOC_SSPMOSI_R: R196.2 U30.L27(SPI0SIMO)
SOC_TIMI0_FPGA_1V8: R162.1 U30.J2(TIMI0_AVSIFSEL0) ; also on sheet 28
SOC_TIMI1_FPGA_1V8: R209.1 U30.J1(TIMI1_AVSIFSEL1) ; also on sheet 28
SOC_TIMO0_FPGA_1V8: R161.1 R181.2 ; also on sheet 28
SOC_TIMO1_FPGA_1V8: R160.1 R180.2 ; also on sheet 28
SOC_TSCOMPOUT: U30.AG1(TSCOMPOUT) ; also on sheet 28
SOC_TSREFCLKN: C181.1 R882.2 ; also on sheet 11
SOC_TSREFCLKN_NET: C181.2 U30.AK14(TSREFCLKN)
SOC_TSREFCLKP: C176.1 R882.1 ; also on sheet 11
SOC_TSREFCLKP_NET: C176.2 U30.AK13(TSREFCLKP)
SOC_TSRXCLKOUT0N: U30.AJ13(TSRXCLKOUT0N) ; also on sheet 26 28
SOC_TSRXCLKOUT0P: U30.AJ12(TSRXCLKOUT0P) ; also on sheet 26 28
SOC_TSSYNCEVT: U30.AG2(TSSYNCEVT) ; also on sheet 28
SOC_UART0_RXD_1V8: U30.K5(UART0RXD_DONE_SERDESTEST_8) ; also on sheet 8
SOC_UART0_TXD_1V8: R604.2 ; also on sheet 8
SOC_UART1_CTS_1V8: R174.1 ; also on sheet 8
SOC_UART1_RTS_1V8: R591.1 ; also on sheet 8
SOC_UART1_TXD_1V8: R185.1 ; also on sheet 22
SYSREFREQ_TCON_FPGA_3V3: CN8.7 ; also on sheet 27
TDD_TIME_SYNC_3V3_TIMINGCON: R376.1 ; also on sheet 27
TSPUSHEVt0_E: U30.AF1(TSPUSHEVT0) ; also on sheet 26
TSPUSHEVt1_E: U30.AH1(TSPUSHEVT1) ; also on sheet 26
UART1_RXD_M: U30.L5(UART1RXD) ; also on sheet 22
N17638330: R731.1 U46.R15(SUSPEND)
N17965264: D8.1(ANODE) R411.1
N17965892: CN14.5 R816.2
N17965910: CN14.3 R815.2
N17968374: R487.1 U46.F5(TDI)
N17979994: TP77.1 U30.K28(SPI0SCS1)
N17979996: TP75.1 U30.K30(SPI0SCS2)
N17979998: TP72.1 U30.K29(SPI0SCS3)
N17980021: TP74.1 U30.M29(SPI0SCS4)
N17980105: R185.2 U30.J5(UART1TXD)
N17980142: R174.2 R175.2 U30.K4(UART1CTS_SPI2SOMI)
N17980148: R587.2 R591.2 U30.J4(UART1RTS_SPI2SIMO)
N19249083: CN8.8 R388.1
N19249112: CN8.9 R376.2
N19620418: CN14.7 R813.1
N19720946: R181.1 U30.H3(TIMO0_CSISC20MUX_SERDESTEST_10)
N19720947: R180.1 U30.J3(TIMO1_CSISC20CLKCTL)
N19720948: R594.1 U30.L4(UART0CTS_SPI2CLK)
N19720949: R597.1 U30.K2(UART0RTS_SPI2SCS0)
N19720950: R604.1 U30.K3(UART0TXD_PASS_SERDESTEST_9)
N21152047: CN8.1 R400.2
N21152085: CN8.3 R393.2

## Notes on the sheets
sheet 29
- FPGA, FPGA JTAG, FPGA-Flash, FPGA Programmer, K2L SPI/TIM/UART, FPGA test conn
- Must be High During Configuration
  to allow configuration to start
- SoC
- BOOT
  MODE pins
sheet 30
- POWER CONSUMPTION
sheet 31
- SCHEMATIC PAGE CONTENT
- 1 : COVER PAGE
  2 : TABLE OF CONTENTS
  3 : BLOCK DIAGRAM
  4 : PLACEMENT
  5 : POWER CONSUMPTION
  6 : POWER SEQUENCE
  7 : POWER DISTRIBUTION
  8 : CLOCK DISTRIBUTION
  9 : BMC BLOCK DIAGRAM
  10 : FMC Interface to JESD/RF devices-1
  11 : FMC Interface to JESD/RF devices - 2
  12 : JESD Serdes switch - 1
  13 : JESD Serdes switch -2
  14 : SGMII/PCIe Serdes switch
  15 : FPGA, SYSREF Buffering, LEDs
  16 : FPGA, FPGA 2pin conn, SPI Flash, LEDs
  17 : FPGA, K2L SPI/TIM/UART, FPGA test conn
  18 : K2L LVDS SigMux, Clock Mux, K2L Reset, K2L CML Serdes JESD/AIL,
  19 : K2L DDR3
  20 : DDR3(3)
  21 : DDR3(2), 3.3vaux -> .75v DDR3 Vt, DDR3 SPD EEPROM
  22 : K2L GND AND POWER
  23 : K2L USB3, TPS USB 5v isolation, USB Type A connector, magnetics, filter, SOC UART 1.8/3.3v, USB to dual UART
  24 : K2L EMU, K2L JTAG, EMU MIPI 60,  EMU Detect, AMC/XDS200
  25 : USIM, SOC UART 1.8v switching, 1.8v/3.3v GPIO INT, SOC UART, GPS
  26 : Expansion Connector, I2C SOC to Expander 1.8v/3.3vAux
  27 : K2L EMIF, VDD and VSSMON, EMIFWAIT1 bfr, NAND Flash, I2C EEPROM
  28 : EMIF Addr/Cntl Buffer, Ext EMIF_OE, EMIF Data Transceiver
  29 : BMC Processor (LM3S2D93), switches, DIPsw, UART Rx Mux, LEDs
  30 : LCD, LCD Power, BMC USB for UART, 4pin UART for BMC, BMC
  31 : AMC connector
  32 : SOC Temp, UCD9090, PMBus Pgm conn, VID Isolator for PMBus
  33 : Ethernet PHY, Magnetics for 2 channel/ Tx/Rx,
  34 : Ethernet PHY, Magnetics for 2 channel/ Tx/Rx
  35 : CDCM62008 Clk1, 122.88/19.2, Power Filter for Clock,
  36 : CDCM62008 Clk2, 100 / 156.25, Power Filter for Clock
  37 : XDS200 / AM1802, flash, USB connector for Emulator
  38 : XDS200 / AM1802,  boot mode, reset, XDS200 power
  39 : XDS200 / debug hdr, oscillators
  40 : XDS200 Power
  41 : XDS200 Emulation CPLD
  42 : 12v input (fused), 12v to 3p3v MP, K2L VID, 1p8 to VPP1p8 switch, 3v3Aux to 3v3, FMC1 Power (fuse),
  43 : Top Avatar, 12v to CVVD , 12v to 1.5v, 3.3v aux -> 1.2v, 3.3v aux -> 1.8v
  44 : LM26430, 12v -> CVVD1, 1v8, v85, 5v
  45 : K2L CVVD, CVVD1, bypass caps, K2L 1v8, K2L 1v0 PLL, caps, filters
  46 : K2L VDDALV, v85 filter, bypass caps, 12v -> 3.3vaux
  47 : REVISION HISTORY
sheet 32
- BMC BLOCK DIAGRAM
